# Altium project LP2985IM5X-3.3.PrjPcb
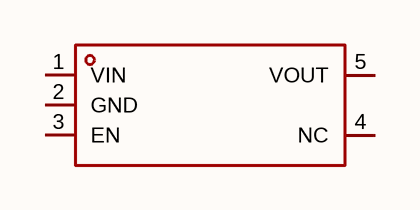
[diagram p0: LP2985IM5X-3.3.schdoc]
1 sheet, 1 parts. Net scope: global (net labels, ports and power ports of the same name join across sheets).

## Sheet LP2985IM5X-3.3.schdoc
size 127 x 101 mm

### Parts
U?  lp2985im5x-3.3  [SOT-23-5_L2.9-W1.6-P0.95-LS2.8-BR]  (value not drawn)

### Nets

Not connected (* = marked no-connect by the designer): U? 1(VIN) 2(GND) 3(EN) 4(NC) 5(VOUT)

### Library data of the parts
U? = lp2985im5x-3.3: 输出极性:正极;工作电压:16V;输出电压:3.3V;输出电流:200mA;电源纹波抑制比(PSRR):70dB@(1kHz);输出类型:固定;; Manufacturer: TECH PUBLIC(台舟); AddInBom: yes; ModelId: 7ba65df16e7b4570af156e925f9c37fe; ModelTransform: 114.173,114.173,0,90,0,0,0,0,0; Output Configuration: 正极; Voltage - Supply: 16V; Output Voltage: 3.3V; Output Current: 200mA; Voltage Dropout: 420mV@(100mA); standby current: 5uA; Output Type: 固定; Number of Outputs: 1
